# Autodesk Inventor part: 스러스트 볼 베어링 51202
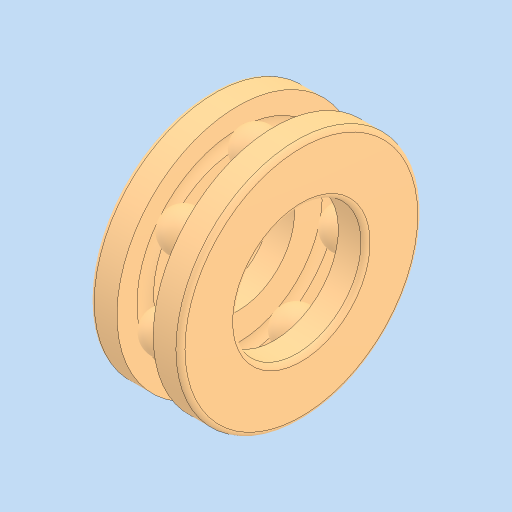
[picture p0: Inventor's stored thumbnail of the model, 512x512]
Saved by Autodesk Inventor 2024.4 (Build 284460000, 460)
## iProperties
Created: 2026-07
Part Number: 스러스트 볼 베어링 51202
Material: 강철, 연강
Description: 롤링 베어링 - 플랫 뒷면이 있는 스러스트 볼 베어링
Document SubType Name: Modeling
Designer: home
Density: 7.85 g/cm^3
Appearance: 기본값
Author: jhkim
Sending System: Autodesk Inventor 2027
Preprocessor: ST-DEVELOPER v20.1
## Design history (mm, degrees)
feature "Solid1"
feature "Solid1:1"
feature "Solid1:2"
feature "Solid1:3"
feature "Solid1:4"
feature "Solid1:5"
feature "Solid1:6"
feature "Solid1:7"
feature "Solid1:8"
node "솔리드1"
node "솔리드2"
node "솔리드3"
node "솔리드4"
node "솔리드5"
node "솔리드6"
node "솔리드7"
node "솔리드8"
node "솔리드9"
